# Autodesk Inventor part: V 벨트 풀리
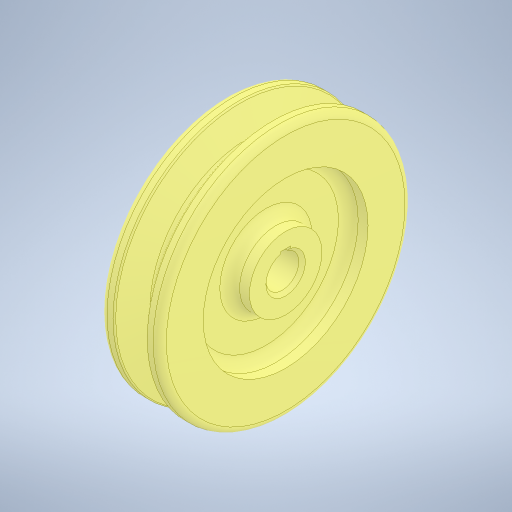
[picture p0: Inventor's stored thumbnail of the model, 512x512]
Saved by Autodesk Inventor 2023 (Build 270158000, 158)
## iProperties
Created: 2025-10
Part Number: V 벨트 풀리
Material: 강철, 주조
Document SubType Name: Modeling
Designer: home
Density: 7.85 g/cm^3
Appearance: 기본값
Author: jhkim
Sending System: Autodesk Inventor 2026
Preprocessor: ST-DEVELOPER v20.1
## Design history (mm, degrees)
sketch "스케치1"
  geometry: 1 further point
  constraints: 1 other
feature "솔리드1"
node "솔리드2"
